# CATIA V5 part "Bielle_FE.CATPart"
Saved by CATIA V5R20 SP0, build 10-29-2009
Part number: Bielle_FE
Bounding box of the stored display mesh (mm): x 0 to 11, y -131.868 to 128.704, z 58.932 to 99.814
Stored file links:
  D:\Dropbox\IAO_2012\IAO_2012_753_jrecappe\jrecappe.zip\Bielle_FE.CATPart
  D:\Dropbox\IAO_2012\IAO_2012_753_jrecappe\jrecappe.zip\Ass_brevetIAO_skl.CATProduct
  D:\Dropbox\IAO_2012\IAO_2012_753_jrecappe\jrecappe.zip\Ass_skl_levier2bras.CATProduct
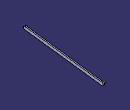
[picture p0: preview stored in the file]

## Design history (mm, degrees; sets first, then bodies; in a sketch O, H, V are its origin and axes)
Set1
  DatumPoint1 "Point F": linked copy from another document
  DatumPoint2 "Point E": linked copy from another document
Body1 (main body)
  Sketch1 on yz-plane, origin (0, 0, 0), H (0, 1, 0), V (0, 0, 1)
    construction line L1 (-127.3306, 95.2723) -> (124.1671, 63.4733)
    point P1 (-127.3306, 95.2723)
    point P2 (124.1671, 63.4733)
    line L2 (-126.7607, 99.7794) -> (124.7369, 67.9804)
    line L3 (123.5972, 58.9662) -> (-127.9005, 90.7652)
    arc A1 centre (124.1671, 63.4733) radius 4.543 from (124.7369, 67.9804) to (123.5972, 58.9662) cw
    arc A2 centre (-127.3306, 95.2723) radius 4.543 from (-127.9005, 90.7652) to (-126.7607, 99.7794) cw
    reference projected point E1 (124.1671, 63.4733) from DatumPoint1
    reference projected point E2 (-127.3306, 95.2723) from DatumPoint2
    distance L1 L2 = 4.543
    tangency: A1 L2, A2 L2, A1 L3, A2 L3
    coincidence: P2 E1, P1 E2
  Pad1: profile Sketch1, direction (1, 0, 0), length 11, opposite side length -7
  Sketch2 on yz-plane, origin (0, 0, 0), H (0, 1, 0), V (0, 0, 1)
    circle A1 centre (124.1671, 63.4733) radius 2.5
    point P1 (124.1671, 63.4733)
    reference projected point E1 (124.1671, 63.4733) from DatumPoint1
    coincidence: P1 E1
  Pad2: profile Sketch2, direction (1, 0, 0), length 11
  Sketch3 on yz-plane, origin (0, 0, 0), H (0, 1, 0), V (0, 0, 1)
    circle A1 centre (-127.3306, 95.2723) radius 2.5
    point P1 (-127.3306, 95.2723)
    reference projected point E1 (-127.3306, 95.2723) from DatumPoint2
    coincidence: P1 E1
  Pad3: profile Sketch3, direction (1, 0, 0), length 11, opposite side length -3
